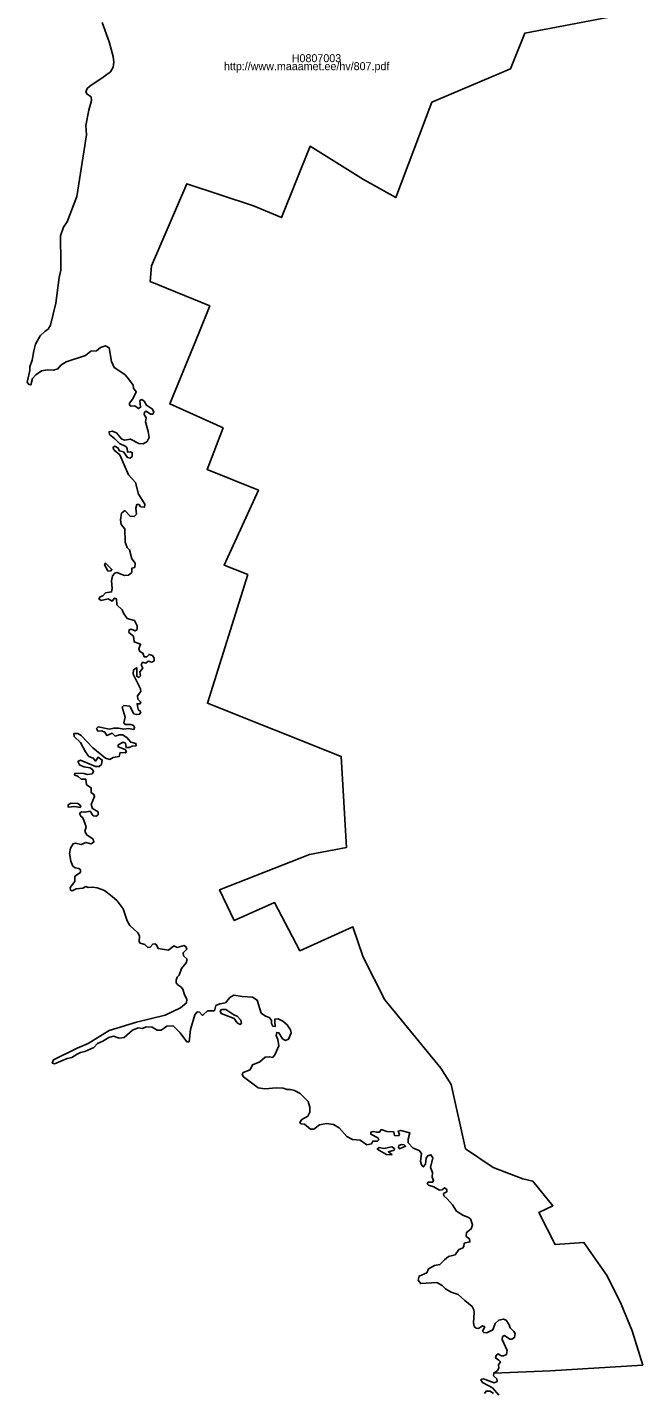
# Model space of a CAD drawing. Extents: x 369010 to 739155, y 6377141 to 6634081.
# Drawn here: x 380465 to 382386, y 6423577 to 6427842 of the extents above; entities that cross this region are included whole.
import ezdxf

# ---------------------------------------------------------------- set-up
doc = ezdxf.new("R2010")
doc.units = 0
for name, color, linetype in [('H_LINK', 7, 'Continuous'), ('H_PIIR', 7, 'Continuous'), ('H_TUNNUS', 7, 'Continuous')]:
    doc.layers.add(name, color=color, linetype=linetype)

msp = doc.modelspace()

# ---------------------------------------------------------------- linework, layer by layer
at = {"layer": 'H_PIIR'}
for points in [[(382281.6301, 6427873.2), (382018.57, 6427823.8699), (381973.73, 6427712.37), (381727.9, 6427607.5701), (381615.1901, 6427310.18), (381513.96, 6427365.99), (381348.34, 6427470.2401), (381258.37, 6427247.73), (381170.8801, 6427284.5001), (380962.5901, 6427353.2), (380851.96, 6427096.3501), (380847.7901, 6427048.08), (381034.46, 6426971.5999), (381000.0199, 6426886.49), (380909.9499, 6426665.47), (381075.6701, 6426590.2699), (381025.88, 6426460.77), (381186.07, 6426395.68), (381079.1001, 6426162.1299), (381153.11, 6426132.33), (381027.0799, 6425730.5299), (381445.14, 6425564.3499), (381461.39, 6425280.34), (381345.7101, 6425257.5101), (381064.99, 6425148.07), (381110.8901, 6425051.35), (381236.81, 6425107.58), (381315.6599, 6424957.22), (381481.2399, 6425031.69), (381513.0701, 6424937.36), (381581.45, 6424804.12), (381755.47, 6424590.15), (381788.7099, 6424540), (381832.9, 6424338.9401), (381918.95, 6424279.9899), (382011.94, 6424245.09), (382042.8, 6424237.11), (382105.28, 6424160.47), (382062.51, 6424139.8399), (382113.0701, 6424039.23), (382202.71, 6424045.48), (382274.9, 6423941.9701), (382319.44, 6423853.26), (382353.32, 6423769.9499), (382386.32, 6423662.87), (382097.4901, 6423644.97), (381921.24, 6423638.1047), (381932.5401, 6423646.3046), (381936.9699, 6423652.9547), (381935.8599, 6423663.8046), (381941.84, 6423672.8946), (381937.1901, 6423678.8746), (381926.7801, 6423685.7446), (381928.55, 6423693.2846), (381934.53, 6423698.1547), (381944.0601, 6423692.1747), (381952.0399, 6423691.5146), (381960.6799, 6423696.6046), (381963.34, 6423708.7946), (381947.3799, 6423742.4747), (381948.4899, 6423752.0046), (381954.4701, 6423755.1147), (381971.0899, 6423744.0346), (381978.18, 6423744.4746), (381985.4999, 6423749.1246), (381987.9301, 6423761.3146), (381983.5, 6423767.7447), (381972.1999, 6423779.2646), (381968.8801, 6423788.7946), (381959.5699, 6423803.8646), (381951.37, 6423806.7446), (381936.9699, 6423803.8646), (381925.4499, 6423792.7847), (381918.5799, 6423773.2846), (381899.3, 6423763.3147), (381889.7701, 6423764.4147), (381886.45, 6423769.0747), (381892.88, 6423782.1446), (381886.01, 6423785.4746), (381873.82, 6423777.0547), (381866.0699, 6423778.1547), (381859.6399, 6423783.6946), (381857.87, 6423795.4447), (381860.2999, 6423826.9146), (381858.74, 6423835.7746), (381854.31, 6423845.9646), (381830.3801, 6423864.5846), (381810, 6423883.4246), (381787.84, 6423891.1746), (381770.7799, 6423901.3746), (381759.9299, 6423911.7946), (381743.3101, 6423921.5446), (381693.23, 6423917.7747), (381684.8099, 6423928.1847), (381688.13, 6423941.2646), (381712.0601, 6423951.2347), (381717.38, 6423963.2046), (381736.66, 6423973.6146), (381753.0501, 6423976.9446), (381767.4601, 6423992.0146), (381780.31, 6424001.9846), (381801.14, 6424007.9647), (381812.65, 6424024.5847), (381823.2899, 6424027.9146), (381827.9399, 6424033.0046), (381829.05, 6424044.3047), (381846.5501, 6424047.8546), (381845, 6424056.9447), (381835.25, 6424065.1447), (381836.36, 6424077.5546), (381850.32, 6424088.1847), (381854.75, 6424101.2647), (381848.0999, 6424119.6546), (381842.12, 6424124.3046), (381824.17, 6424131.4047), (381804.66, 6424144.2546), (381792.47, 6424163.5346), (381775.86, 6424182.1447), (381765, 6424191.8947), (381764.33, 6424198.5446), (381774.2999, 6424204.7547), (381774.52, 6424211.6247), (381767.66, 6424216.9446), (381759.68, 6424210.7346), (381751.9201, 6424209.8547), (381733.75, 6424219.3846), (381717.58, 6424224.6946), (381713.37, 6424229.3547), (381716.0299, 6424234.0047), (381730.21, 6424234.2246), (381733.3099, 6424239.5446), (381728.44, 6424250.1847), (381730.21, 6424264.3646), (381723.34, 6424280.5446), (381730.87, 6424310.0146), (381724.89, 6424319.9847), (381715.36, 6424316.8846), (381710.49, 6424308.9046), (381708.0501, 6424290.9546), (381701.1801, 6424282.3146), (381695.1999, 6424288.2947), (381692.76, 6424299.6046), (381695.1999, 6424324.1947), (381688.55, 6424333.2847), (381669.9401, 6424340.5946), (381653.55, 6424357.6547), (381653.55, 6424368.7346), (381659.31, 6424388.4546), (381630.7301, 6424395.9946), (381622.31, 6424393.7747), (381626.52, 6424383.8046), (381623.63, 6424378.9347), (381611.6701, 6424380.0347), (381609.01, 6424391.5647), (381587.07, 6424392.6747), (381570.0099, 6424398.8746), (381564.47, 6424390.8947), (381554.4999, 6424390.2346), (381544.7501, 6424392.2247), (381537.2199, 6424390.4547), (381537.66, 6424384.2546), (381559.37, 6424372.7246), (381562.25, 6424366.9646), (381558.0401, 6424362.0947), (381544.0799, 6424362.7547), (381539.6501, 6424354.3346), (381524.81, 6424351.0146), (381504.4201, 6424366.0747), (381480.27, 6424367.6346), (381462.0999, 6424377.1547), (381438.36, 6424404.6146), (381420.6099, 6424414.8346), (381398.55, 6424417.5247), (381377.2999, 6424414.0347), (381359.5401, 6424400.3047), (381349.32, 6424399.4946), (381330.22, 6424415.6446), (381319.1901, 6424416.4447), (381315.96, 6424420.4847), (381322.15, 6424430.4346), (381340.4399, 6424440.3946), (381346.8901, 6424452.7747), (381347.16, 6424469.1846), (381341.5099, 6424486.1347), (381316.2199, 6424511.4346), (381299.28, 6424520.5746), (381286.36, 6424524.0746), (381276.4099, 6424523.5346), (381263.7701, 6424527.5746), (381242.25, 6424528.6446), (381206.2, 6424526.2346), (381185.48, 6424529.4647), (381139.48, 6424563.3646), (381135.7101, 6424570.8946), (381138.4, 6424576.8147), (381160.4601, 6424584.8947), (381167.73, 6424601.0347), (381190.86, 6424610.7247), (381207, 6424624.4446), (381219.9201, 6424626.3247), (381230.9401, 6424623.9046), (381239.0201, 6424634.3947), (381249.51, 6424660.4947), (381247.0901, 6424679.8646), (381241.98, 6424692.5146), (381243.32, 6424702.1946), (381250.05, 6424700.5846), (381261.88, 6424682.2847), (381271.3001, 6424677.1747), (381280.4399, 6424681.2147), (381289.0499, 6424701.3947), (381286.9001, 6424710.2746), (381275.8701, 6424725.8746), (381262.96, 6424736.9046), (381248.1601, 6424744.7147), (381237.94, 6424743.9046), (381237.6699, 6424735.8346), (381239.0201, 6424720.7646), (381231.75, 6424721.5747), (381226.9101, 6424729.9146), (381226.64, 6424740.9446), (381220.18, 6424748.7447), (381208.8899, 6424753.0546), (381195.1701, 6424762.4647), (381182.25, 6424803.3646), (381168.26, 6424812.5146), (381135.44, 6424814.3947), (381109.6199, 6424818.4347), (381097.5099, 6424810.8946), (381083.26, 6424794.2147), (381066.04, 6424791.2546), (381053.6599, 6424785.8746), (381049.0899, 6424769.7346), (381027.03, 6424769.4647), (381014.12, 6424756.8147), (381010.63, 6424756.0046), (381002.02, 6424765.6946), (380995.02, 6424766.2346), (380987.76, 6424757.3547), (380974.31, 6424710.8046), (380969.73, 6424672.8646), (380962.4699, 6424672.8646), (380942.2899, 6424701.1246), (380919.69, 6424722.6446), (380899.78, 6424721.5647), (380882.2999, 6424709.4647), (380869.6499, 6424709.1946), (380854.87, 6424718.6046), (380835.23, 6424719.6846), (380823.93, 6424714.0347), (380810.48, 6424716.1846), (380793.5301, 6424708.9147), (380767.4399, 6424686.5846), (380751.8299, 6424684.7047), (380733.27, 6424690.8946), (380719.28, 6424686.0546), (380700.45, 6424674.7546), (380684.04, 6424667.2146), (380671.93, 6424654.5747), (380643.9499, 6424642.4647), (380631.04, 6424639.2347), (380619.7399, 6424634.1246), (380603.5999, 6424624.1647), (380588.52, 6424620.6647), (380549.24, 6424603.9847), (380542.25, 6424606.4046), (380546.0101, 6424616.3646), (380620, 6424652.6846), (380654.17, 6424667.2146), (380720.08, 6424708.3747), (380805.91, 6424734.2147), (380895.4999, 6424755.7347), (380943.11, 6424779.4147), (380961.4001, 6424794.2147), (380962.21, 6424805.7847), (380955.48, 6424819.2347), (380949.8299, 6424837.5347), (380943.65, 6424844.7946), (380934.5, 6424850.4446), (380929.39, 6424856.9046), (380929.6599, 6424865.2447), (380932.9, 6424874.6646), (380939.09, 6424881.1146), (380945.8099, 6424902.1047), (380960.8801, 6424919.5947), (380963.3, 6424931.1647), (380952, 6424941.9247), (380951.19, 6424950.8047), (380962.76, 6424962.3746), (380960.8801, 6424968.8346), (380953.8799, 6424973.6747), (380932.6301, 6424967.4847), (380921.6001, 6424972.5947), (380905.73, 6424959.1446), (380873.1801, 6424964.5247), (380868.07, 6424975.8246), (380862.96, 6424979.3146), (380856.23, 6424978.2446), (380847.89, 6424968.0147), (380840.63, 6424967.4847), (380831.21, 6424976.3546), (380816.6801, 6424981.2047), (380813.45, 6424986.0446), (380814.7999, 6425003.8047), (380809.96, 6425013.4847), (380784.9401, 6425036.3546), (380776.59, 6425050.3546), (380763.4099, 6425088.5647), (380745.38, 6425112.7747), (380729.24, 6425127.0346), (380705.3001, 6425145.3346), (380682.43, 6425154.2146), (380669.5201, 6425156.0947), (380654.72, 6425154.4747), (380647.73, 6425157.7047), (380638.04, 6425152.8646), (380616.79, 6425150.4447), (380604.95, 6425144.2546), (380599.5699, 6425146.6746), (380598.76, 6425154.4747), (380613.29, 6425173.3147), (380612.75, 6425190.2646), (380630.7799, 6425201.8346), (380630.51, 6425210.1746), (380625.4, 6425214.7446), (380613.5601, 6425215.8246), (380606.83, 6425221.7447), (380600.65, 6425237.6146), (380596.61, 6425261.0247), (380599.3, 6425277.4446), (380607.37, 6425290.8946), (380615.1699, 6425293.3147), (380632.39, 6425288.7447), (380646.9199, 6425295.4646), (380662.5201, 6425290.8946), (380672.2099, 6425296.0046), (380670.33, 6425305.6946), (380650.69, 6425319.1546), (380643.7, 6425329.6447), (380647.9999, 6425344.7147), (380638.3201, 6425372.6946), (380631.59, 6425377.5347), (380627.56, 6425386.1446), (380633.7401, 6425391.2546), (380644.5, 6425389.9146), (380660.65, 6425393.6847), (380670.6001, 6425379.1546), (380679.2099, 6425377.5347), (380685.94, 6425382.1146), (380685.4, 6425390.7246), (380667.91, 6425401.4846), (380664.1399, 6425413.8546), (380674.6401, 6425439.1546), (380672.2199, 6425445.6047), (380663.6099, 6425451.2546), (380663.6099, 6425466.3246), (380649.3501, 6425476.0146), (380647.21, 6425493.2546), (380633.22, 6425493.2546), (380623.8099, 6425501.3246), (380611.97, 6425506.4347), (380613.31, 6425511.5547), (380640.76, 6425511.0147), (380652.0499, 6425508.3246), (380666.5801, 6425510.2046), (380671.42, 6425516.9346), (380668.73, 6425522.5847), (380660.93, 6425528.5046), (380641.2901, 6425532.0046), (380627.03, 6425538.4546), (380622.46, 6425548.1446), (380630.53, 6425552.4547), (380677.6101, 6425532.5346), (380689.1801, 6425532.8047), (380696.4499, 6425539.2647), (380698.3301, 6425552.7246), (380685.6801, 6425561.8646), (380677.34, 6425549.7646), (380670.35, 6425558.6446), (380657.17, 6425564.2946), (380645.8701, 6425578.2846), (380630.53, 6425607.6146), (380610.35, 6425626.9847), (380609.82, 6425635.8646), (380622.46, 6425635.5947), (380633.22, 6425629.4046), (380669.5401, 6425591.1947), (380708.82, 6425558.6446), (380722.27, 6425554.8747), (380732.76, 6425561.0647), (380751.8699, 6425564.5547), (380754.2901, 6425576.3946), (380770.16, 6425575.3146), (380773.9301, 6425578.5447), (380769.9001, 6425586.3546), (380748.64, 6425593.8846), (380748.64, 6425600.0746), (380763.4399, 6425608.4147), (380771.5099, 6425605.7246), (380773.12, 6425592.0046), (380782.27, 6425591.7347), (380791.96, 6425596.8447), (380804.33, 6425597.6546), (380803.7899, 6425605.1846), (380787.38, 6425608.4147), (380775.28, 6425623.2146), (380762.09, 6425631.8246), (380752.95, 6425631.5547), (380738.6901, 6425628.0547), (380729.5401, 6425636.9346), (380713.13, 6425629.4046), (380706.4001, 6425639.8946), (380696.99, 6425643.9346), (380684.88, 6425643.6647), (380680.85, 6425651.1947), (380685.6901, 6425656.8447), (380720.93, 6425649.5846), (380734.6501, 6425653.0846), (380748.91, 6425653.0846), (380766.13, 6425649.3147), (380779.31, 6425651.1947), (380796.8, 6425648.7747), (380799.49, 6425654.9646), (380796.53, 6425660.8847), (380787.6499, 6425664.3847), (380770.16, 6425663.8447), (380766.13, 6425669.7646), (380769.9001, 6425686.4447), (380760.48, 6425718.4646), (380766.4001, 6425723.5846), (380784.7, 6425721.6946), (380797.6101, 6425697.2047), (380806.49, 6425694.7846), (380815.8999, 6425696.4046), (380818.59, 6425703.3946), (380810.52, 6425711.2047), (380807.2999, 6425728.9647), (380816.17, 6425728.1546), (380819.3999, 6425733.8046), (380809.7201, 6425743.2246), (380808.64, 6425753.4446), (380818.8599, 6425766.6347), (380818.06, 6425775.5146), (380794.6501, 6425820.9846), (380796.2599, 6425834.7047), (380806.49, 6425841.4347), (380806.2201, 6425814.7946), (380812.94, 6425811.2946), (380817.7901, 6425816.4046), (380815.8999, 6425828.7847), (380825.05, 6425839.5546), (380819.9499, 6425850.3147), (380824.5299, 6425858.3847), (380834.75, 6425855.1546), (380842.28, 6425861.8846), (380853.0401, 6425858.9247), (380860.3099, 6425862.6946), (380860.3099, 6425871.0347), (380855.1999, 6425879.3746), (380844.7, 6425882.8746), (380837.9801, 6425875.8746), (380829.3701, 6425875.6047), (380825.6, 6425887.1747), (380816.19, 6425892.0246), (380813.2301, 6425900.6346), (380818.07, 6425914.8947), (380798.43, 6425921.8846), (380796.55, 6425939.6447), (380781.75, 6425951.7547), (380782.5601, 6425959.2947), (380788.48, 6425962.2547), (380801.12, 6425956.3347), (380807.58, 6425960.3647), (380807.3099, 6425972.7446), (380799.2399, 6425988.8846), (380776.6399, 6425995.6147), (380764.8, 6426012.2947), (380760.77, 6426021.9846), (380744.3499, 6426037.5846), (380742.7401, 6426056.1547), (380736.55, 6426058.3046), (380729.83, 6426049.4246), (380716.6399, 6426056.1547), (380695.3899, 6426051.8446), (380688.3999, 6426056.1547), (380691.62, 6426062.6147), (380700.4999, 6426065.5746), (380708.84, 6426075.5246), (380727.94, 6426077.9446), (380729.29, 6426088.7146), (380727.1401, 6426112.6647), (380730.9, 6426128.5346), (380737.6301, 6426136.8747), (380744.3499, 6426139.0246), (380768.3, 6426129.6146), (380780.67, 6426130.9546), (380790.6301, 6426139.0246), (380791.1699, 6426152.4847), (380800.3099, 6426154.9047), (380801.6601, 6426167.8146), (380790.6301, 6426181.8046), (380783.36, 6426209.5246), (380776.0999, 6426216.7846), (380769.64, 6426233.7446), (380768.5699, 6426274.9047), (380758.08, 6426289.1647), (380755.9199, 6426303.1647), (380759.15, 6426323.8747), (380769.3801, 6426332.4847), (380785.5201, 6426314.4646), (380798.43, 6426313.3847), (380805.97, 6426321.4546), (380803.2699, 6426339.4847), (380807.04, 6426351.3246), (380813.7701, 6426351.3246), (380818.07, 6426344.0647), (380830.4501, 6426342.7146), (380831.79, 6426351.8646), (380811.8799, 6426383.6146), (380802.1901, 6426420.4846), (380780.93, 6426443.6246), (380753.2201, 6426506.8547), (380735.7399, 6426521.3846), (380731.6999, 6426529.1847), (380737.35, 6426533.7646), (380747.04, 6426527.8446), (380752.4199, 6426518.4247), (380764.79, 6426515.4647), (380776.9, 6426498.5146), (380785.24, 6426496.0946), (380792.5, 6426501.4746), (380792.5, 6426513.0447), (380786.85, 6426516.0047), (380777.4401, 6426514.6546), (380776.63, 6426526.7646), (380771.79, 6426532.4146), (380752.95, 6426541.2947), (380737.07, 6426557.7047), (380721.4701, 6426569.8147), (380719.85, 6426578.4247), (380729.5401, 6426580.3046), (380742.99, 6426574.9247), (380758.3301, 6426556.6246), (380768.55, 6426552.5946), (380786.31, 6426555.8247), (380812.4, 6426541.5546), (380826.66, 6426540.7547), (380838.77, 6426547.7447), (380844.9601, 6426560.1246), (380842.26, 6426579.7646), (380836.35, 6426597.5246), (380833.9101, 6426609.3646), (380836.0699, 6426621.7347), (380829.61, 6426632.5047), (380830.69, 6426639.2246), (380835.8, 6426643.2646), (380849.5201, 6426633.8447), (380856.78, 6426633.5746), (380859.7399, 6426640.0347), (380855.98, 6426649.1846), (380837.14, 6426661.0246), (380829.3401, 6426674.2047), (380822.61, 6426678.7847), (380816.43, 6426675.8247), (380818.3101, 6426655.1047), (380811.8499, 6426650.7946), (380800.02, 6426659.9446), (380788.9901, 6426658.8746), (380784.1399, 6426661.0246), (380783.34, 6426668.2847), (380793.5601, 6426681.2046), (380804.86, 6426703.2646), (380795.98, 6426714.2946), (380794.6399, 6426724.5246), (380780.38, 6426743.8947), (380769.08, 6426756.8146), (380736.2699, 6426778.8746), (380727.93, 6426797.7147), (380719.86, 6426841.0346), (380709.1, 6426846.9546), (380692.96, 6426842.1147), (380680.3199, 6426831.3446), (380662.83, 6426830.2746), (380645.8801, 6426817.0846), (380585.8701, 6426796.9047), (380569.19, 6426786.1447), (380560.3199, 6426775.1147), (380546.33, 6426770.8046), (380527.4899, 6426771.8846), (380509.2, 6426768.9246), (380490.91, 6426756.5447), (380480.41, 6426745.2446), (380475.5699, 6426725.3346), (380469.1099, 6426726.1347), (380464.5399, 6426733.4046), (380472.34, 6426769.4646), (380472.34, 6426781.2946), (380479.88, 6426802.5546), (380484.7199, 6426831.0747), (380490.1001, 6426851.7947), (380504.63, 6426878.4247), (380520.4999, 6426892.6847), (380529.38, 6426898.6047), (380536.91, 6426910.9846), (380553.32, 6426980.4047), (380563.53, 6427060.0547), (380569.45, 6427083.1947), (380569.18, 6427105.2547), (380568.3899, 6427190.0047), (380577.27, 6427217.7247), (380589.1, 6427234.1346), (380618.7101, 6427312.9846), (380649.1, 6427506.1747), (380647.22, 6427535.2346), (380656.36, 6427583.1146), (380665.5001, 6427612.9847), (380663.6199, 6427624.5546), (380651.5199, 6427632.6246), (380646.9401, 6427640.7046), (380650.9801, 6427650.6546), (380663.89, 6427661.1546), (380697.52, 6427682.9446), (380724.42, 6427702.8547), (380733.0301, 6427716.8447), (380735.1799, 6427732.9947), (380733.0301, 6427750.4846), (380720.1199, 6427796.4946), (380698.06, 6427856.5046)], [(381937.1901, 6423569.4047), (381916.8099, 6423592.2346), (381885.7901, 6423608.6347), (381880.69, 6423616.6047), (381883.8, 6423619.4847), (381889.33, 6423620.1547), (381922.1301, 6423607.3046), (381931.66, 6423611.2846), (381930.99, 6423620.3746), (381919.91, 6423629.9047), (381921.24, 6423638.1), (382097.4901, 6423644.97), (382386.32, 6423662.87), (382353.32, 6423769.9499), (382319.44, 6423853.26), (382274.9, 6423941.9701), (382202.71, 6424045.48), (382113.0701, 6424039.23), (382062.51, 6424139.8399), (382105.28, 6424160.47), (382042.8, 6424237.11), (382011.94, 6424245.09), (381918.95, 6424279.9899), (381832.9, 6424338.9401), (381788.7099, 6424540), (381755.47, 6424590.15), (381581.45, 6424804.12), (381513.0701, 6424937.36), (381481.2399, 6425031.69), (381315.6599, 6424957.22), (381236.81, 6425107.58), (381110.8901, 6425051.35), (381064.99, 6425148.07), (381345.7101, 6425257.5101), (381461.39, 6425280.34), (381445.14, 6425564.3499), (381027.0799, 6425730.5299), (381153.11, 6426132.33), (381079.1001, 6426162.1299), (381186.07, 6426395.68), (381025.88, 6426460.77), (381075.6701, 6426590.2699), (380909.9499, 6426665.47), (381000.0199, 6426886.49), (381034.46, 6426971.5999), (380847.7901, 6427048.08), (380851.96, 6427096.3501), (380962.5901, 6427353.2), (381170.8801, 6427284.5001), (381258.37, 6427247.73), (381348.34, 6427470.2401), (381513.96, 6427365.99), (381615.1901, 6427310.18), (381727.9, 6427607.5701), (381973.73, 6427712.37), (382018.57, 6427823.8699), (382281.6301, 6427873.2)], [(381892.21, 6423574.2846), (381897.09, 6423582.0347), (381909.5, 6423581.1546), (381919.91, 6423574.2846)]]:
    msp.add_lwpolyline(points, dxfattribs=at)
for points in [[(380724.4142, 6426142.7495), (380715.6425, 6426143.577), (380705.8776, 6426162.61), (380709.1879, 6426168.4025), (380728.7172, 6426148.7076)], [(380629.9114, 6425404.9326), (380612.6989, 6425407.4151), (380592.3419, 6425405.7601), (380592.3419, 6425413.5388), (380600.4517, 6425418.1729), (380622.6292, 6425417.0145), (380631.4009, 6425410.3942)], [(381128.4093, 6424726.8628), (381118.4792, 6424733.6483), (381110.2039, 6424745.5648), (381069.821, 6424761.6186), (381066.8419, 6424768.5698), (381071.476, 6424773.5349), (381084.0543, 6424773.7003), (381109.3764, 6424756.819), (381120.2997, 6424752.8469), (381131.7195, 6424740.5995), (381133.0434, 6424730.5038)], [(381604.0679, 6424320.054), (381586.1934, 6424320.3849), (381557.5612, 6424337.7628), (381563.3538, 6424342.7279), (381577.9183, 6424339.9144), (381602.7438, 6424344.3829), (381611.6811, 6424339.0869), (381609.8604, 6424334.4528), (381592.3171, 6424329.6532)], [(381633.362, 6424352.3273), (381641.3062, 6424351.4998), (381645.9404, 6424346.3691), (381627.2385, 6424338.0939), (381623.2663, 6424343.2245), (381624.9215, 6424349.0171)]]:
    msp.add_lwpolyline(points, close=True, dxfattribs=at)

# ---------------------------------------------------------------- texts
at = {"layer": 'H_LINK'}
msp.add_text('http://www.maaamet.ee/hv/807.pdf', height=25, rotation=360, dxfattribs=at).set_placement((381078.6076, 6427707.9194))
at = {"layer": 'H_TUNNUS'}
msp.add_text('H0807003', height=25, rotation=360, dxfattribs=at).set_placement((381290.4621, 6427732.9194))

doc.saveas('drawing.dxf')
